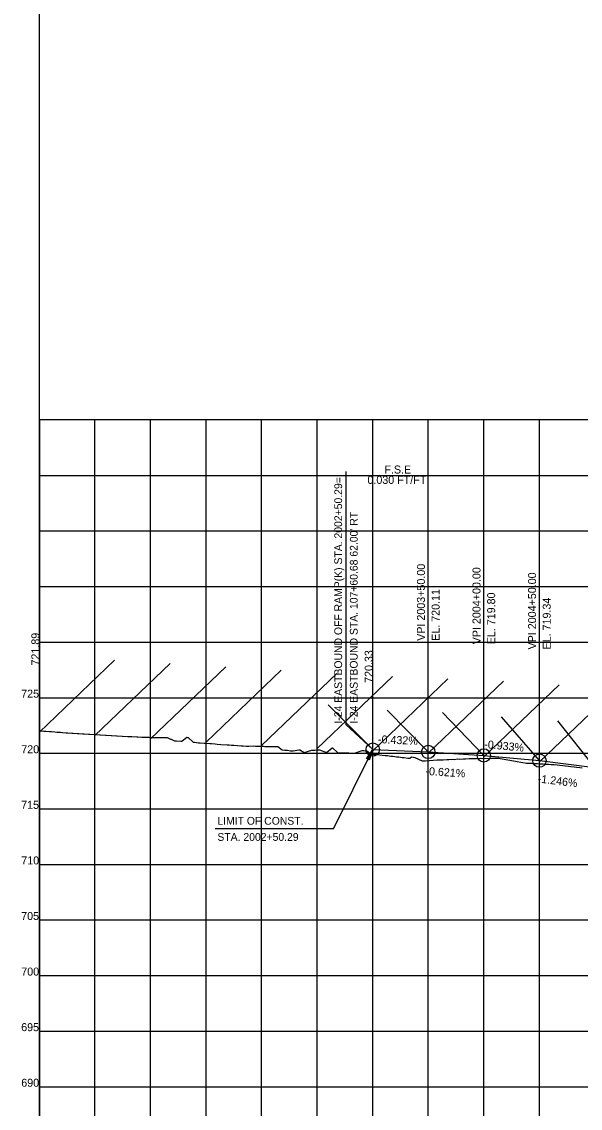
# Model space of a CAD drawing. Extents: x -7164 to 2214450, y -19642 to 253469.
# Drawn here: x 5984 to 6487, y 381 to 1358 of the extents above; entities that cross this region are included whole.
import ezdxf

# ---------------------------------------------------------------- set-up
doc = ezdxf.new("R2010")
doc.units = 0
for name, color, linetype in [('DESIGN - PROFILE - Proposed', 7, 'Continuous'), ('DESIGN - PROFILE - Proposed Curve Text', 7, 'Continuous'), ('DESIGN - PROFILE - Proposed Text', 7, 'Continuous'), ('DESIGN - SCRATCH - User 1', 7, 'Continuous'), ('DESIGN - SHEET - Light Grid', 7, 'Continuous'), ('SURVEY - PROFILE - Ground Line with Text', 7, 'Continuous'), ('XTREE', 7, 'Continuous')]:
    doc.layers.add(name, color=color, linetype=linetype)

msp = doc.modelspace()

# ---------------------------------------------------------------- linework, layer by layer
at = {"layer": 'DESIGN - PROFILE - Proposed'}
for p, q in [((6300, 703.29), (6350, 701.13)), ((6300, 703.29), (6350, 701.13)), ((6350, 701.13), (6400, 698.03)), ((6350, 701.13), (6400, 698.03)), ((6400, 698.03), (6450, 693.36)), ((6400, 698.03), (6450, 693.36)), ((6450, 693.36), (6500, 687.14)), ((6450, 693.36), (6500, 687.14))]:
    msp.add_line(p, q, dxfattribs=at)
at = {"layer": 'DESIGN - PROFILE - Proposed Curve Text'}
msp.add_line((6000, 950), (6672.59, 950), dxfattribs=at)
msp.add_line((6000, 950), (6672.59, 950), dxfattribs=at)
at = {"layer": 'DESIGN - PROFILE - Proposed Text'}
for p, q in [((6275.94, 953.36), (6275.94, 725.74)), ((6275.94, 953.36), (6275.94, 725.74)), ((6264.85, 631.96), (6300, 703.29)), ((6264.85, 631.96), (6300, 703.29)), ((6264.85, 631.96), (6158.2, 631.96)), ((6264.85, 631.96), (6158.2, 631.96))]:
    msp.add_line(p, q, dxfattribs=at)
for points in [[(6275.94, 725.74), (6300, 703.29)], [(6275.94, 725.74), (6300, 703.29)], [(6300, 703.29), (6296.68, 693.73), (6296.13, 695.44), (6294.39, 694.85), (6300, 703.29)], [(6300, 703.29), (6296.68, 693.73), (6296.13, 695.44), (6294.39, 694.85), (6300, 703.29)]]:
    msp.add_lwpolyline(points, dxfattribs=at)
msp.add_lwpolyline([(6300, 703.29), (6296.68, 693.73), (6296.13, 695.44), (6294.39, 694.85)], close=True, dxfattribs=at)
msp.add_lwpolyline([(6300, 703.29), (6296.68, 693.73), (6296.13, 695.44), (6294.39, 694.85)], close=True, dxfattribs=at)
for centre in [(6300, 703.29), (6300, 703.29), (6350, 701.13), (6350, 701.13), (6400, 698.03), (6400, 698.03), (6450, 693.36), (6450, 693.36)]:
    msp.add_circle(centre, 6, dxfattribs=at)
at = {"layer": 'DESIGN - SCRATCH - User 1'}
for p, q in [((6000, 0), (6000, 1327.38)), ((6000, 0), (6000, 1327.38)), ((9700, 1000), (6000, 1000)), ((6000, 1000), (6000, 0)), ((9700, 1000), (6000, 1000)), ((6000, 1000), (6000, 0)), ((6300, 703.29), (6259.82, 743.61)), ((6300, 703.29), (6259.82, 743.61)), ((6350, 701.13), (6313.06, 738.63)), ((6350, 701.13), (6313.06, 738.63)), ((6400, 698.03), (6362.89, 736.53)), ((6400, 698.03), (6362.89, 736.53)), ((6450, 693.36), (6415.87, 732.85)), ((6450, 693.36), (6415.87, 732.85)), ((6500, 687.14), (6466.7, 729.31)), ((6500, 687.14), (6466.7, 729.31))]:
    msp.add_line(p, q, dxfattribs=at)
at = {"layer": 'DESIGN - SHEET - Light Grid'}
for p, q in [((6000, 0), (6000, 2500)), ((6000, 0), (6000, 2500)), ((6050, 0), (6050, 1000)), ((6050, 0), (6050, 1000)), ((6100, 0), (6100, 1000)), ((6100, 0), (6100, 1000)), ((6150, 0), (6150, 1000)), ((6150, 0), (6150, 1000)), ((6200, 0), (6200, 1000)), ((6200, 0), (6200, 1000)), ((6250, 0), (6250, 1000)), ((6250, 0), (6250, 1000)), ((6300, 0), (6300, 1000)), ((6300, 0), (6300, 1000)), ((6350, 0), (6350, 1000)), ((6350, 0), (6350, 1000)), ((6400, 0), (6400, 1000)), ((6400, 0), (6400, 1000)), ((6450, 0), (6450, 1000)), ((6450, 0), (6450, 1000)), ((6000, 950), (9700, 950)), ((6000, 950), (9700, 950)), ((6000, 900), (9700, 900)), ((6000, 900), (9700, 900)), ((6000, 850), (9700, 850)), ((6000, 850), (9700, 850)), ((6000, 800), (9700, 800)), ((6000, 800), (9700, 800)), ((6000, 750), (9700, 750)), ((6000, 750), (9700, 750)), ((6000, 700), (9700, 700)), ((6000, 700), (9700, 700)), ((6000, 650), (9700, 650)), ((6000, 650), (9700, 650)), ((6000, 600), (9700, 600)), ((6000, 600), (9700, 600)), ((6000, 550), (9700, 550)), ((6000, 550), (9700, 550)), ((6000, 500), (9700, 500)), ((6000, 500), (9700, 500)), ((6000, 450), (9700, 450)), ((6000, 450), (9700, 450)), ((6000, 400), (9700, 400)), ((6000, 400), (9700, 400))]:
    msp.add_line(p, q, dxfattribs=at)
at = {"layer": 'SURVEY - PROFILE - Ground Line with Text'}
for points in [[(6000, 720.14), (6000.99, 720.08), (6003.95, 719.94), (6005.92, 719.83), (6008.97, 719.58), (6010.83, 719.47), (6014.02, 719.2), (6015.75, 719.1), (6019.06, 718.82), (6020.68, 718.72), (6024.1, 718.43), (6025.6, 718.33), (6029.14, 718.04), (6030.53, 717.95), (6034.19, 717.74), (6035.45, 717.66), (6039.23, 717.45), (6040.37, 717.38), (6044.28, 717.16), (6045.28, 717.1), (6049.32, 716.88), (6050.2, 716.82), (6054.37, 716.59), (6054.39, 716.59), (6055.14, 716.54), (6059.44, 716.3), (6060.05, 716.26), (6064.49, 716.01), (6064.95, 715.98), (6069.54, 715.73), (6069.86, 715.71), (6074.59, 715.44), (6074.76, 715.43), (6079.65, 715.16), (6079.67, 715.16), (6080.41, 715.11), (6083.05, 714.97), (6083.35, 714.97), (6087.69, 714.75), (6088.52, 714.73), (6092.33, 714.55), (6093.68, 714.53), (6096.97, 714.38), (6098.84, 714.35), (6101.6, 714.24), (6104.01, 714.21), (6106.24, 714.13), (6109.17, 714.11), (6110.88, 714.05), (6113.3, 714.03), (6114.06, 714.03), (6115.15, 714.02), (6118.07, 712.63), (6118.52, 712.59), (6121.62, 711.28), (6123.3, 711.15), (6127.32, 710.83), (6128.31, 710.74), (6132.74, 714.33), (6133.32, 714.28), (6133.9, 714.23), (6138.31, 709.92), (6139.51, 709.84), (6143.32, 709.52), (6144.6, 709.45), (6148.33, 709.14), (6149.69, 709.06), (6153.33, 708.76), (6154.78, 708.67), (6158.34, 708.38), (6159.87, 708.29), (6163.34, 708), (6168.87, 707.72), (6170.95, 707.57), (6172.96, 707.42), (6174.9, 707.28), (6178.36, 707.05), (6181.58, 706.82), (6183.36, 706.74), (6186.53, 706.51), (6188.37, 706.43), (6192.94, 706.56), (6194.42, 706.43), (6195.8, 706.31), (6201.64, 706.23), (6203, 706.11), (6204.26, 706), (6211.93, 706.13), (6213.26, 706.02), (6214.5, 705.93), (6218.41, 703.22), (6220.92, 702.86), (6223.42, 702.63), (6226.05, 702.26), (6228.42, 702.03), (6233.52, 703.09), (6233.88, 703.03), (6234.29, 702.96), (6238.44, 700.8), (6245.27, 702.82), (6246.49, 702.82)], [(6000, 720.14), (6000.99, 720.08), (6003.95, 719.94), (6005.92, 719.83), (6008.97, 719.58), (6010.83, 719.47), (6014.02, 719.2), (6015.75, 719.1), (6019.06, 718.82), (6020.68, 718.72), (6024.1, 718.43), (6025.6, 718.33), (6029.14, 718.04), (6030.53, 717.95), (6034.19, 717.74), (6035.45, 717.66), (6039.23, 717.45), (6040.37, 717.38), (6044.28, 717.16), (6045.28, 717.1), (6049.32, 716.88), (6050.2, 716.82), (6054.37, 716.59), (6054.39, 716.59), (6055.14, 716.54), (6059.44, 716.3), (6060.05, 716.26), (6064.49, 716.01), (6064.95, 715.98), (6069.54, 715.73), (6069.86, 715.71), (6074.59, 715.44), (6074.76, 715.43), (6079.65, 715.16), (6079.67, 715.16), (6080.41, 715.11), (6083.05, 714.97), (6083.35, 714.97), (6087.69, 714.75), (6088.52, 714.73), (6092.33, 714.55), (6093.68, 714.53), (6096.97, 714.38), (6098.84, 714.35), (6101.6, 714.24), (6104.01, 714.21), (6106.24, 714.13), (6109.17, 714.11), (6110.88, 714.05), (6113.3, 714.03), (6114.06, 714.03), (6115.15, 714.02), (6118.07, 712.63), (6118.52, 712.59), (6121.62, 711.28), (6123.3, 711.15), (6127.32, 710.83), (6128.31, 710.74), (6132.74, 714.33), (6133.32, 714.28), (6133.9, 714.23), (6138.31, 709.92), (6139.51, 709.84), (6143.32, 709.52), (6144.6, 709.45), (6148.33, 709.14), (6149.69, 709.06), (6153.33, 708.76), (6154.78, 708.67), (6158.34, 708.38), (6159.87, 708.29), (6163.34, 708), (6168.87, 707.72), (6170.95, 707.57), (6172.96, 707.42), (6174.9, 707.28), (6178.36, 707.05), (6181.58, 706.82), (6183.36, 706.74), (6186.53, 706.51), (6188.37, 706.43), (6192.94, 706.56), (6194.42, 706.43), (6195.8, 706.31), (6201.64, 706.23), (6203, 706.11), (6204.26, 706), (6211.93, 706.13), (6213.26, 706.02), (6214.5, 705.93), (6218.41, 703.22), (6220.92, 702.86), (6223.42, 702.63), (6226.05, 702.26), (6228.42, 702.03), (6233.52, 703.09), (6233.88, 703.03), (6234.29, 702.96), (6238.44, 700.8), (6245.27, 702.82), (6246.49, 702.82)], [(6000, 720.14), (6000.99, 720.08), (6003.95, 719.94), (6005.92, 719.83), (6008.97, 719.58), (6010.83, 719.47), (6014.02, 719.2), (6015.75, 719.1), (6019.06, 718.82), (6020.68, 718.72), (6024.1, 718.43), (6025.6, 718.33), (6029.14, 718.04), (6030.53, 717.95), (6034.19, 717.74), (6035.45, 717.66), (6039.23, 717.45), (6040.37, 717.38), (6044.28, 717.16), (6045.28, 717.1), (6049.32, 716.88), (6050.2, 716.82), (6054.37, 716.59), (6054.39, 716.59), (6055.14, 716.54), (6059.44, 716.3), (6060.05, 716.26), (6064.49, 716.01), (6064.95, 715.98), (6069.54, 715.73), (6069.86, 715.71), (6074.59, 715.44), (6074.76, 715.43), (6079.65, 715.16), (6079.67, 715.16), (6080.41, 715.11), (6083.05, 714.97), (6083.35, 714.97), (6087.69, 714.75), (6088.52, 714.73), (6092.33, 714.55), (6093.68, 714.53), (6096.97, 714.38), (6098.84, 714.35), (6101.6, 714.24), (6104.01, 714.21), (6106.24, 714.13), (6109.17, 714.11), (6110.88, 714.05), (6113.3, 714.03), (6114.06, 714.03), (6115.15, 714.02), (6118.07, 712.63), (6118.52, 712.59), (6121.62, 711.28), (6123.3, 711.15), (6127.32, 710.83), (6128.31, 710.74), (6132.74, 714.33), (6133.32, 714.28), (6133.9, 714.23), (6138.31, 709.92), (6139.51, 709.84), (6143.32, 709.52), (6144.6, 709.45), (6148.33, 709.14), (6149.69, 709.06), (6153.33, 708.76), (6154.78, 708.67), (6158.34, 708.38), (6159.87, 708.29), (6163.34, 708), (6168.87, 707.72), (6170.95, 707.57), (6172.96, 707.42), (6174.9, 707.28), (6178.36, 707.05), (6181.58, 706.82), (6183.36, 706.74), (6186.53, 706.51), (6188.37, 706.43), (6192.94, 706.56), (6194.42, 706.43), (6195.8, 706.31), (6201.64, 706.23), (6203, 706.11), (6204.26, 706), (6211.93, 706.13), (6213.26, 706.02), (6214.5, 705.93), (6218.41, 703.22), (6220.92, 702.86), (6223.42, 702.63), (6226.05, 702.26), (6228.42, 702.03), (6233.52, 703.09), (6233.88, 703.03), (6234.29, 702.96), (6238.44, 700.8), (6245.27, 702.82), (6246.49, 702.82)], [(6000, 720.14), (6000.99, 720.08), (6003.95, 719.94), (6005.92, 719.83), (6008.97, 719.58), (6010.83, 719.47), (6014.02, 719.2), (6015.75, 719.1), (6019.06, 718.82), (6020.68, 718.72), (6024.1, 718.43), (6025.6, 718.33), (6029.14, 718.04), (6030.53, 717.95), (6034.19, 717.74), (6035.45, 717.66), (6039.23, 717.45), (6040.37, 717.38), (6044.28, 717.16), (6045.28, 717.1), (6049.32, 716.88), (6050.2, 716.82), (6054.37, 716.59), (6054.39, 716.59), (6055.14, 716.54), (6059.44, 716.3), (6060.05, 716.26), (6064.49, 716.01), (6064.95, 715.98), (6069.54, 715.73), (6069.86, 715.71), (6074.59, 715.44), (6074.76, 715.43), (6079.65, 715.16), (6079.67, 715.16), (6080.41, 715.11), (6083.05, 714.97), (6083.35, 714.97), (6087.69, 714.75), (6088.52, 714.73), (6092.33, 714.55), (6093.68, 714.53), (6096.97, 714.38), (6098.84, 714.35), (6101.6, 714.24), (6104.01, 714.21), (6106.24, 714.13), (6109.17, 714.11), (6110.88, 714.05), (6113.3, 714.03), (6114.06, 714.03), (6115.15, 714.02), (6118.07, 712.63), (6118.52, 712.59), (6121.62, 711.28), (6123.3, 711.15), (6127.32, 710.83), (6128.31, 710.74), (6132.74, 714.33), (6133.32, 714.28), (6133.9, 714.23), (6138.31, 709.92), (6139.51, 709.84), (6143.32, 709.52), (6144.6, 709.45), (6148.33, 709.14), (6149.69, 709.06), (6153.33, 708.76), (6154.78, 708.67), (6158.34, 708.38), (6159.87, 708.29), (6163.34, 708), (6168.87, 707.72), (6170.95, 707.57), (6172.96, 707.42), (6174.9, 707.28), (6178.36, 707.05), (6181.58, 706.82), (6183.36, 706.74), (6186.53, 706.51), (6188.37, 706.43), (6192.94, 706.56), (6194.42, 706.43), (6195.8, 706.31), (6201.64, 706.23), (6203, 706.11), (6204.26, 706), (6211.93, 706.13), (6213.26, 706.02), (6214.5, 705.93), (6218.41, 703.22), (6220.92, 702.86), (6223.42, 702.63), (6226.05, 702.26), (6228.42, 702.03), (6233.52, 703.09), (6233.88, 703.03), (6234.29, 702.96), (6238.44, 700.8), (6245.27, 702.82), (6246.49, 702.82)], [(6246.49, 702.82), (6247.77, 702.81), (6249.89, 703.05), (6250.29, 703.05), (6251.05, 703.1), (6252.18, 703.16), (6258.45, 700.65), (6263.58, 704.93), (6263.68, 704.93), (6263.78, 704.93), (6268.45, 700.57), (6270.46, 700.52), (6273.45, 700.41), (6275.49, 700.35), (6278.45, 700.25), (6280.52, 700.19), (6283.45, 700.08), (6290.51, 702.4), (6291.92, 702.37), (6293.27, 702.22), (6294.63, 702.08), (6298.45, 699.14), (6301.33, 698.83), (6303.45, 698.74), (6306.34, 698.44), (6308.45, 698.35), (6311.34, 698.04), (6313.44, 697.95), (6316.41, 697.48), (6318.42, 697.39), (6321.47, 696.89), (6323.41, 696.8), (6326.54, 696.29), (6328.41, 696.2), (6331.62, 695.67), (6333.4, 695.58), (6334.88, 696.79), (6337.9, 696.21), (6337.92, 696.2), (6344.37, 693.3), (6345.41, 693.29), (6346.4, 693.27), (6347.37, 693.25), (6357.85, 694.11), (6358.7, 694.09), (6359.52, 694.08), (6363.4, 694.11), (6366.57, 694.41), (6368.4, 694.29), (6371.62, 694.61), (6373.39, 694.49), (6376.67, 694.83), (6378.38, 694.71), (6381.73, 695.07), (6383.38, 694.96), (6386.8, 695.34), (6388.36, 695.23), (6391.81, 695.4), (6393.36, 695.27), (6396.85, 695.44), (6398.36, 695.32), (6401.89, 695.5), (6403.36, 695.38), (6406.93, 695.57), (6408.36, 695.45), (6411.97, 695.65), (6413.36, 695.53), (6414.78, 695.34), (6418.36, 694.64), (6419.85, 694.45), (6423.36, 693.76), (6424.91, 693.56), (6428.36, 692.88), (6429.98, 692.68), (6433.36, 692.02), (6435.05, 691.81), (6438.35, 691.17), (6438.38, 691.16), (6440.12, 690.96), (6443.37, 690.98), (6445.27, 690.76), (6448.36, 690.76), (6450.42, 690.52), (6453.34, 690.5), (6455.54, 690.24), (6458.33, 690.22), (6460.66, 689.94), (6463.32, 689.9), (6463.41, 689.9), (6466.02, 689.53), (6468.4, 689.33), (6471.09, 688.95), (6473.4, 688.74), (6476.17, 688.35), (6478.39, 688.15), (6481.26, 687.74), (6483.39, 687.55), (6486.34, 687.13), (6488.38, 686.94)], [(6246.49, 702.82), (6247.77, 702.81), (6249.89, 703.05), (6250.29, 703.05), (6251.05, 703.1), (6252.18, 703.16), (6258.45, 700.65), (6263.58, 704.93), (6263.68, 704.93), (6263.78, 704.93), (6268.45, 700.57), (6270.46, 700.52), (6273.45, 700.41), (6275.49, 700.35), (6278.45, 700.25), (6280.52, 700.19), (6283.45, 700.08), (6290.51, 702.4), (6291.92, 702.37), (6293.27, 702.22), (6294.63, 702.08), (6298.45, 699.14), (6301.33, 698.83), (6303.45, 698.74), (6306.34, 698.44), (6308.45, 698.35), (6311.34, 698.04), (6313.44, 697.95), (6316.41, 697.48), (6318.42, 697.39), (6321.47, 696.89), (6323.41, 696.8), (6326.54, 696.29), (6328.41, 696.2), (6331.62, 695.67), (6333.4, 695.58), (6334.88, 696.79), (6337.9, 696.21), (6337.92, 696.2), (6344.37, 693.3), (6345.41, 693.29), (6346.4, 693.27), (6347.37, 693.25), (6357.85, 694.11), (6358.7, 694.09), (6359.52, 694.08), (6363.4, 694.11), (6366.57, 694.41), (6368.4, 694.29), (6371.62, 694.61), (6373.39, 694.49), (6376.67, 694.83), (6378.38, 694.71), (6381.73, 695.07), (6383.38, 694.96), (6386.8, 695.34), (6388.36, 695.23), (6391.81, 695.4), (6393.36, 695.27), (6396.85, 695.44), (6398.36, 695.32), (6401.89, 695.5), (6403.36, 695.38), (6406.93, 695.57), (6408.36, 695.45), (6411.97, 695.65), (6413.36, 695.53), (6414.78, 695.34), (6418.36, 694.64), (6419.85, 694.45), (6423.36, 693.76), (6424.91, 693.56), (6428.36, 692.88), (6429.98, 692.68), (6433.36, 692.02), (6435.05, 691.81), (6438.35, 691.17), (6438.38, 691.16), (6440.12, 690.96), (6443.37, 690.98), (6445.27, 690.76), (6448.36, 690.76), (6450.42, 690.52), (6453.34, 690.5), (6455.54, 690.24), (6458.33, 690.22), (6460.66, 689.94), (6463.32, 689.9), (6463.41, 689.9), (6466.02, 689.53), (6468.4, 689.33), (6471.09, 688.95), (6473.4, 688.74), (6476.17, 688.35), (6478.39, 688.15), (6481.26, 687.74), (6483.39, 687.55), (6486.34, 687.13), (6488.38, 686.94)], [(6246.49, 702.82), (6247.77, 702.81), (6249.89, 703.05), (6250.29, 703.05), (6251.05, 703.1), (6252.18, 703.16), (6258.45, 700.65), (6263.58, 704.93), (6263.68, 704.93), (6263.78, 704.93), (6268.45, 700.57), (6270.46, 700.52), (6273.45, 700.41), (6275.49, 700.35), (6278.45, 700.25), (6280.52, 700.19), (6283.45, 700.08), (6290.51, 702.4), (6291.92, 702.37), (6293.27, 702.22), (6294.63, 702.08), (6298.45, 699.14), (6301.33, 698.83), (6303.45, 698.74), (6306.34, 698.44), (6308.45, 698.35), (6311.34, 698.04), (6313.44, 697.95), (6316.41, 697.48), (6318.42, 697.39), (6321.47, 696.89), (6323.41, 696.8), (6326.54, 696.29), (6328.41, 696.2), (6331.62, 695.67), (6333.4, 695.58), (6334.88, 696.79), (6337.9, 696.21), (6337.92, 696.2), (6344.37, 693.3), (6345.41, 693.29), (6346.4, 693.27), (6347.37, 693.25), (6357.85, 694.11), (6358.7, 694.09), (6359.52, 694.08), (6363.4, 694.11), (6366.57, 694.41), (6368.4, 694.29), (6371.62, 694.61), (6373.39, 694.49), (6376.67, 694.83), (6378.38, 694.71), (6381.73, 695.07), (6383.38, 694.96), (6386.8, 695.34), (6388.36, 695.23), (6391.81, 695.4), (6393.36, 695.27), (6396.85, 695.44), (6398.36, 695.32), (6401.89, 695.5), (6403.36, 695.38), (6406.93, 695.57), (6408.36, 695.45), (6411.97, 695.65), (6413.36, 695.53), (6414.78, 695.34), (6418.36, 694.64), (6419.85, 694.45), (6423.36, 693.76), (6424.91, 693.56), (6428.36, 692.88), (6429.98, 692.68), (6433.36, 692.02), (6435.05, 691.81), (6438.35, 691.17), (6438.38, 691.16), (6440.12, 690.96), (6443.37, 690.98), (6445.27, 690.76), (6448.36, 690.76), (6450.42, 690.52), (6453.34, 690.5), (6455.54, 690.24), (6458.33, 690.22), (6460.66, 689.94), (6463.32, 689.9), (6463.41, 689.9), (6466.02, 689.53), (6468.4, 689.33), (6471.09, 688.95), (6473.4, 688.74), (6476.17, 688.35), (6478.39, 688.15), (6481.26, 687.74), (6483.39, 687.55), (6486.34, 687.13), (6488.38, 686.94)], [(6246.49, 702.82), (6247.77, 702.81), (6249.89, 703.05), (6250.29, 703.05), (6251.05, 703.1), (6252.18, 703.16), (6258.45, 700.65), (6263.58, 704.93), (6263.68, 704.93), (6263.78, 704.93), (6268.45, 700.57), (6270.46, 700.52), (6273.45, 700.41), (6275.49, 700.35), (6278.45, 700.25), (6280.52, 700.19), (6283.45, 700.08), (6290.51, 702.4), (6291.92, 702.37), (6293.27, 702.22), (6294.63, 702.08), (6298.45, 699.14), (6301.33, 698.83), (6303.45, 698.74), (6306.34, 698.44), (6308.45, 698.35), (6311.34, 698.04), (6313.44, 697.95), (6316.41, 697.48), (6318.42, 697.39), (6321.47, 696.89), (6323.41, 696.8), (6326.54, 696.29), (6328.41, 696.2), (6331.62, 695.67), (6333.4, 695.58), (6334.88, 696.79), (6337.9, 696.21), (6337.92, 696.2), (6344.37, 693.3), (6345.41, 693.29), (6346.4, 693.27), (6347.37, 693.25), (6357.85, 694.11), (6358.7, 694.09), (6359.52, 694.08), (6363.4, 694.11), (6366.57, 694.41), (6368.4, 694.29), (6371.62, 694.61), (6373.39, 694.49), (6376.67, 694.83), (6378.38, 694.71), (6381.73, 695.07), (6383.38, 694.96), (6386.8, 695.34), (6388.36, 695.23), (6391.81, 695.4), (6393.36, 695.27), (6396.85, 695.44), (6398.36, 695.32), (6401.89, 695.5), (6403.36, 695.38), (6406.93, 695.57), (6408.36, 695.45), (6411.97, 695.65), (6413.36, 695.53), (6414.78, 695.34), (6418.36, 694.64), (6419.85, 694.45), (6423.36, 693.76), (6424.91, 693.56), (6428.36, 692.88), (6429.98, 692.68), (6433.36, 692.02), (6435.05, 691.81), (6438.35, 691.17), (6438.38, 691.16), (6440.12, 690.96), (6443.37, 690.98), (6445.27, 690.76), (6448.36, 690.76), (6450.42, 690.52), (6453.34, 690.5), (6455.54, 690.24), (6458.33, 690.22), (6460.66, 689.94), (6463.32, 689.9), (6463.41, 689.9), (6466.02, 689.53), (6468.4, 689.33), (6471.09, 688.95), (6473.4, 688.74), (6476.17, 688.35), (6478.39, 688.15), (6481.26, 687.74), (6483.39, 687.55), (6486.34, 687.13), (6488.38, 686.94)]]:
    msp.add_lwpolyline(points, dxfattribs=at)
at = {"layer": 'XTREE'}
for p, q in [((6000, 718.91), (6067.74, 783.68)), ((6000, 718.91), (6067.74, 783.68)), ((6050, 715.96), (6117.74, 780.73)), ((6050, 715.96), (6117.74, 780.73)), ((6100, 713), (6167.74, 777.77)), ((6100, 713), (6167.74, 777.77)), ((6150, 710.04), (6217.74, 774.81)), ((6150, 710.04), (6217.74, 774.81)), ((6200, 707.09), (6267.74, 771.86)), ((6200, 707.09), (6267.74, 771.86)), ((6250, 704.13), (6317.74, 768.9)), ((6250, 704.13), (6317.74, 768.9)), ((6300, 702.12), (6367.74, 766.89)), ((6300, 702.12), (6367.74, 766.89)), ((6350, 699.96), (6417.74, 764.73)), ((6350, 699.96), (6417.74, 764.73)), ((6400, 696.86), (6467.74, 761.63)), ((6400, 696.86), (6467.74, 761.63)), ((6450, 692.19), (6517.74, 756.96)), ((6450, 692.19), (6517.74, 756.96))]:
    msp.add_line(p, q, dxfattribs=at)

# ---------------------------------------------------------------- texts
at = {"layer": 'DESIGN - PROFILE - Proposed Curve Text'}
for s, p in [('F.S.E', (6310.51, 951.63)), ('0.030 FT/FT', (6295.25, 942.31))]:
    msp.add_text(s, height=7.2, dxfattribs=at).set_placement(p)
for s, rotation, p in [('F.S.E', 360, (6310.51, 951.63)), ('0.030 FT/FT', 360, (6295.25, 942.31)), ('VPI 2003+50.00', 90, (6347, 801.13)), ('VPI 2003+50.00', 90, (6347, 801.13)), ('VPI 2004+00.00', 90, (6397, 798.03)), ('VPI 2004+00.00', 90, (6397, 798.03)), ('VPI 2004+50.00', 90, (6447, 793.36)), ('VPI 2004+50.00', 90, (6447, 793.36)), ('EL. 720.11', 90, (6360.2, 801.13)), ('EL. 720.11', 90, (6360.2, 801.13)), ('EL. 719.80', 90, (6410.2, 798.03)), ('EL. 719.80', 90, (6410.2, 798.03)), ('EL. 719.34', 90, (6460.2, 793.36)), ('EL. 719.34', 90, (6460.2, 793.36)), ('721.89', 90, (6000, 778.91)), ('721.89', 90, (6000, 778.91)), ('720.33', 90, (6300, 763.29)), ('720.33', 90, (6300, 763.29))]:
    msp.add_text(s, height=7.2, rotation=rotation, dxfattribs=at).set_placement(p)
at = {"layer": 'DESIGN - PROFILE - Proposed Text'}
for s, height, rotation, p in [('I-24 EASTBOUND OFF RAMP(K) STA. 2002+50.29=', 7, 90, (6272.44, 726.74)), ('I-24 EASTBOUND OFF RAMP(K) STA. 2002+50.29=', 7, 90, (6272.44, 726.74)), ("I-24 EASTBOUND STA. 107+60.68 62.00' RT", 7, 90, (6286.44, 726.74)), ('I-24 EASTBOUND STA. 107+60.68', 7, 90, (6286.44, 726.74)), ('-0.432%', 7.2, 357.52675, (6304.62, 709.08)), ('-0.432%', 7.2, 357.52675, (6304.62, 709.08)), ('-0.933%', 7.2, 354.66988, (6400.1, 704.7)), ('-0.933%', 7.2, 354.66988, (6400.1, 704.7)), ('-0.621%', 7.2, 356.44836, (6347.28, 680.49)), ('-0.621%', 7.2, 356.44836, (6347.28, 680.49)), ('-1.246%', 7.2, 352.89951, (6448.23, 673.79)), ('-1.246%', 7.2, 352.89951, (6448.23, 673.79))]:
    msp.add_text(s, height=height, rotation=rotation, dxfattribs=at).set_placement(p)
for s, height, p in [('725', 7.2, (5983.62, 750)), ('725', 7.2, (5983.62, 750)), ('720', 7.2, (5983.71, 700)), ('720', 7.2, (5983.71, 700)), ('715', 7.2, (5983.62, 650)), ('715', 7.2, (5983.62, 650)), ('LIMIT OF CONST.', 7, (6160.2, 635.71)), ('LIMIT OF CONST.', 7, (6160.2, 635.71)), ('STA. 2002+50.29', 7, (6160.2, 621.21)), ('STA. 2002+50.29', 7, (6160.2, 621.21)), ('710', 7.2, (5983.71, 600)), ('710', 7.2, (5983.71, 600)), ('705', 7.2, (5983.62, 550)), ('705', 7.2, (5983.62, 550)), ('700', 7.2, (5983.71, 500)), ('700', 7.2, (5983.71, 500)), ('695', 7.2, (5983.62, 450)), ('695', 7.2, (5983.62, 450)), ('690', 7.2, (5983.71, 400)), ('690', 7.2, (5983.71, 400)), ('690', 7.2, (5983.71, 400)), ('690', 7.2, (5983.71, 400))]:
    msp.add_text(s, height=height, dxfattribs=at).set_placement(p)

doc.saveas('drawing.dxf')
